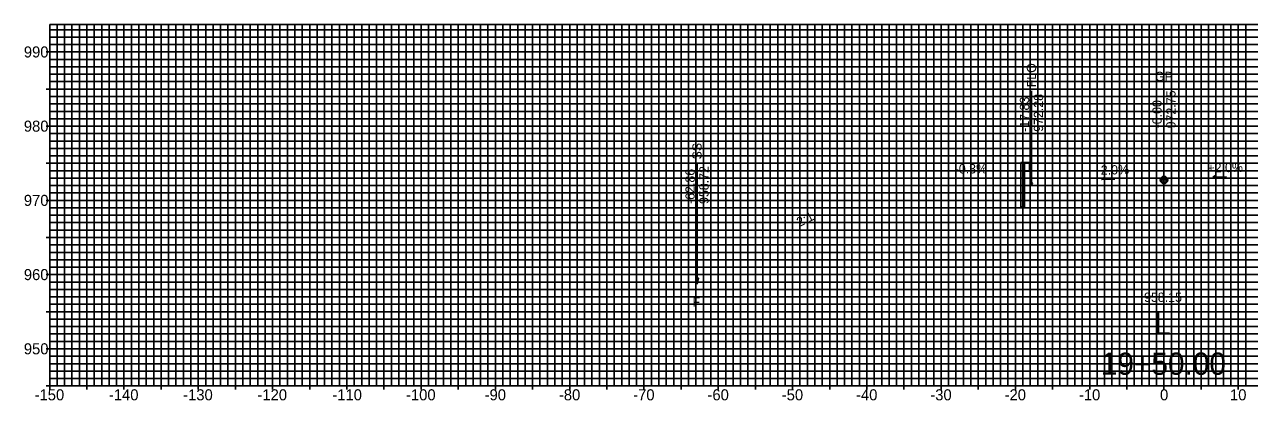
# Model space of a CAD drawing. Extents: x -153 to 153, y 943 to 994.
# Drawn here: x -153.4 to 11.5, y 943 to 993.7 of the extents above; entities that cross this region are included whole.
import ezdxf

# ---------------------------------------------------------------- set-up
doc = ezdxf.new("R2010")
doc.units = 0
for name, color, linetype in [('E_NCDOT_Terrain_Model_Boundary', 7, 'Continuous'), ('E_NCDOT_Terrain_Model_Breakline', 7, 'Continuous'), ('E_NCDOT_Terrain_Model_Hole', 7, 'Continuous'), ('E_NCDOT_Terrain_Model_Island', 7, 'Continuous'), ('E_NCDOT_Terrain_Model_Points_High', 7, 'Continuous'), ('E_NCDOT_Terrain_Model_Points_Low', 7, 'Continuous'), ('E_NCDOT_Terrain_Model_Void', 7, 'Continuous'), ('E_NCDOT_XS_Center_Line_Elevation_Label', 7, 'Continuous'), ('P_NCDOT_XS_Label_Grading_Side_Slope', 7, 'Continuous'), ('P_NCDOT_XS_Label_Slope_Superelevation', 7, 'Continuous'), ('Prop XS Grade Point', 7, 'Continuous'), ('Prop XS Label Slope Superelevation', 7, 'Continuous'), ('Prop XSC Text', 7, 'Continuous'), ('Sheet_Data_Field_CELL', 7, 'Continuous'), ('Sheet_Plan', 7, 'Continuous'), ('Sheet_Sticker_Incomplete_CELL', 7, 'Continuous'), ('z - Construction', 7, 'Continuous')]:
    doc.layers.add(name, color=color, linetype=linetype)

msp = doc.modelspace()

# ---------------------------------------------------------------- linework, layer by layer
at = {"layer": 'E_NCDOT_Terrain_Model_Breakline'}
for p, q in [((-150, 993), (150, 993)), ((-149, 945), (-149, 993.7)), ((-148, 945), (-148, 993.7)), ((-147, 945), (-147, 993.7)), ((-146, 945), (-146, 993.7)), ((-144, 945), (-144, 993.7)), ((-143, 945), (-143, 993.7)), ((-142, 945), (-142, 993.7)), ((-141, 945), (-141, 993.7)), ((-139, 945), (-139, 993.7)), ((-138, 945), (-138, 993.7)), ((-137, 945), (-137, 993.7)), ((-136, 945), (-136, 993.7)), ((-134, 945), (-134, 993.7)), ((-133, 945), (-133, 993.7)), ((-132, 945), (-132, 993.7)), ((-131, 945), (-131, 993.7)), ((-129, 945), (-129, 993.7)), ((-128, 945), (-128, 993.7)), ((-127, 945), (-127, 993.7)), ((-126, 945), (-126, 993.7)), ((-124, 945), (-124, 993.7)), ((-123, 945), (-123, 993.7)), ((-122, 945), (-122, 993.7)), ((-121, 945), (-121, 993.7)), ((-119, 945), (-119, 993.7)), ((-118, 945), (-118, 993.7)), ((-117, 945), (-117, 993.7)), ((-116, 945), (-116, 993.7)), ((-114, 945), (-114, 993.7)), ((-113, 945), (-113, 993.7)), ((-112, 945), (-112, 993.7)), ((-111, 945), (-111, 993.7)), ((-109, 945), (-109, 993.7)), ((-108, 945), (-108, 993.7)), ((-107, 945), (-107, 993.7)), ((-106, 945), (-106, 993.7)), ((-104, 945), (-104, 993.7)), ((-103, 945), (-103, 993.7)), ((-102, 945), (-102, 993.7)), ((-101, 945), (-101, 993.7)), ((-99, 945), (-99, 993.7)), ((-98, 945), (-98, 993.7)), ((-97, 945), (-97, 993.7)), ((-96, 945), (-96, 993.7)), ((-94, 945), (-94, 993.7)), ((-93, 945), (-93, 993.7)), ((-92, 945), (-92, 993.7)), ((-91, 945), (-91, 993.7)), ((-89, 945), (-89, 993.7)), ((-88, 945), (-88, 993.7)), ((-87, 945), (-87, 993.7)), ((-86, 945), (-86, 993.7)), ((-84, 945), (-84, 993.7)), ((-83, 945), (-83, 993.7)), ((-82, 945), (-82, 993.7)), ((-81, 945), (-81, 993.7)), ((-79, 945), (-79, 993.7)), ((-78, 945), (-78, 993.7)), ((-77, 945), (-77, 993.7)), ((-76, 945), (-76, 993.7)), ((-74, 945), (-74, 993.7)), ((-73, 945), (-73, 993.7)), ((-72, 945), (-72, 993.7)), ((-71, 945), (-71, 993.7)), ((-69, 945), (-69, 993.7)), ((-68, 945), (-68, 993.7)), ((-67, 945), (-67, 993.7)), ((-66, 945), (-66, 993.7)), ((-64, 945), (-64, 993.7)), ((-63, 945), (-63, 993.7)), ((-62, 945), (-62, 993.7)), ((-61, 945), (-61, 993.7)), ((-59, 945), (-59, 993.7)), ((-58, 945), (-58, 993.7)), ((-57, 945), (-57, 993.7)), ((-56, 945), (-56, 993.7)), ((-54, 945), (-54, 993.7)), ((-53, 945), (-53, 993.7)), ((-52, 945), (-52, 993.7)), ((-51, 945), (-51, 993.7)), ((-49, 945), (-49, 993.7)), ((-48, 945), (-48, 993.7)), ((-47, 945), (-47, 993.7)), ((-46, 945), (-46, 993.7)), ((-44, 945), (-44, 993.7)), ((-43, 945), (-43, 993.7)), ((-42, 945), (-42, 993.7)), ((-41, 945), (-41, 993.7)), ((-39, 945), (-39, 993.7)), ((-38, 945), (-38, 993.7)), ((-37, 945), (-37, 993.7)), ((-36, 945), (-36, 993.7)), ((-34, 945), (-34, 993.7)), ((-33, 945), (-33, 993.7)), ((-32, 945), (-32, 993.7)), ((-31, 945), (-31, 993.7)), ((-29, 945), (-29, 993.7)), ((-28, 945), (-28, 993.7)), ((-27, 945), (-27, 993.7)), ((-26, 945), (-26, 993.7)), ((-24, 945), (-24, 993.7)), ((-23, 945), (-23, 993.7)), ((-22, 945), (-22, 993.7)), ((-21, 945), (-21, 993.7)), ((-19, 945), (-19, 993.7)), ((-18, 945), (-18, 993.7)), ((-17, 945), (-17, 993.7)), ((-16, 945), (-16, 993.7)), ((-14, 945), (-14, 993.7)), ((-13, 945), (-13, 993.7)), ((-12, 945), (-12, 993.7)), ((-11, 945), (-11, 993.7)), ((-9, 945), (-9, 993.7)), ((-8, 945), (-8, 993.7)), ((-7, 945), (-7, 993.7)), ((-6, 945), (-6, 993.7)), ((-4, 945), (-4, 993.7)), ((-3, 945), (-3, 993.7)), ((-2, 945), (-2, 993.7)), ((-1, 945), (-1, 993.7)), ((1, 945), (1, 993.7)), ((2, 945), (2, 993.7)), ((3, 945), (3, 993.7)), ((4, 945), (4, 993.7)), ((6, 945), (6, 993.7)), ((7, 945), (7, 993.7)), ((8, 945), (8, 993.7)), ((9, 945), (9, 993.7)), ((11, 945), (11, 993.7)), ((-150, 992), (150, 992)), ((-150, 991), (150, 991)), ((-150, 989), (150, 989)), ((-150, 988), (150, 988)), ((-150, 987), (150, 987)), ((-150, 986), (150, 986)), ((-150, 984), (150, 984)), ((-150, 983), (150, 983)), ((-150, 982), (150, 982)), ((-150, 981), (150, 981)), ((-150, 979), (150, 979)), ((-150, 978), (150, 978)), ((-150, 977), (150, 977)), ((-150, 976), (150, 976)), ((-150, 974), (150, 974)), ((-150, 973), (150, 973)), ((-150, 972), (150, 972)), ((-150, 971), (150, 971)), ((-150, 969), (150, 969)), ((-150, 968), (150, 968)), ((-150, 967), (150, 967)), ((-150, 966), (150, 966)), ((-150, 964), (150, 964)), ((-150, 963), (150, 963)), ((-150, 962), (150, 962)), ((-150, 961), (150, 961)), ((-150, 959), (150, 959)), ((-150, 958), (150, 958)), ((-150, 957), (150, 957)), ((-150, 956), (150, 956)), ((-150, 954), (150, 954)), ((-150, 953), (150, 953)), ((-150, 952), (150, 952)), ((-150, 951), (150, 951)), ((-150, 949), (150, 949)), ((-150, 948), (150, 948)), ((-150, 947), (150, 947)), ((-150, 946), (150, 946))]:
    msp.add_line(p, q, dxfattribs=at)
at = {"layer": 'E_NCDOT_Terrain_Model_Island'}
for p, q in [((-140, 945), (-140, 993.7)), ((-130, 945), (-130, 993.7)), ((-120, 945), (-120, 993.7)), ((-110, 945), (-110, 993.7)), ((-100, 945), (-100, 993.7)), ((-90, 945), (-90, 993.7)), ((-80, 945), (-80, 993.7)), ((-70, 945), (-70, 993.7)), ((-60, 945), (-60, 993.7)), ((-50, 945), (-50, 993.7)), ((-40, 945), (-40, 993.7)), ((-30, 945), (-30, 993.7)), ((-20, 945), (-20, 993.7)), ((-10, 945), (-10, 993.7)), ((0, 945), (0, 993.7)), ((10, 945), (10, 993.7)), ((-150, 990), (150, 990)), ((-150, 980), (150, 980)), ((-150, 970), (150, 970)), ((-150, 960), (150, 960)), ((-150, 950), (150, 950))]:
    msp.add_line(p, q, dxfattribs=at)
at = {"layer": 'E_NCDOT_Terrain_Model_Points_High'}
for p, q in [((-145, 945), (-145, 993.7)), ((-140, 945), (-140, 993.7)), ((-135, 945), (-135, 993.7)), ((-130, 945), (-130, 993.7)), ((-125, 945), (-125, 993.7)), ((-120, 945), (-120, 993.7)), ((-115, 945), (-115, 993.7)), ((-110, 945), (-110, 993.7)), ((-105, 945), (-105, 993.7)), ((-100, 945), (-100, 993.7)), ((-95, 945), (-95, 993.7)), ((-90, 945), (-90, 993.7)), ((-85, 945), (-85, 993.7)), ((-80, 945), (-80, 993.7)), ((-75, 945), (-75, 993.7)), ((-70, 945), (-70, 993.7)), ((-65, 945), (-65, 993.7)), ((-60, 945), (-60, 993.7)), ((-55, 945), (-55, 993.7)), ((-50, 945), (-50, 993.7)), ((-45, 945), (-45, 993.7)), ((-40, 945), (-40, 993.7)), ((-35, 945), (-35, 993.7)), ((-30, 945), (-30, 993.7)), ((-25, 945), (-25, 993.7)), ((-20, 945), (-20, 993.7)), ((-15, 945), (-15, 993.7)), ((-10, 945), (-10, 993.7)), ((-5, 945), (-5, 993.7)), ((0, 945), (0, 993.7)), ((5, 945), (5, 993.7)), ((10, 945), (10, 993.7)), ((-150, 990), (-150.48, 990)), ((-150, 990), (150, 990)), ((-150, 985), (-150.48, 985)), ((-150, 985), (150, 985)), ((-150, 980), (-150.48, 980)), ((-150, 980), (150, 980)), ((-150, 975), (-150.48, 975)), ((-150, 975), (150, 975)), ((-150, 970), (-150.48, 970)), ((-150, 970), (150, 970)), ((-150, 965), (-150.48, 965)), ((-150, 965), (150, 965)), ((-150, 960), (-150.48, 960)), ((-150, 960), (150, 960)), ((-150, 955), (-150.48, 955)), ((-150, 955), (150, 955)), ((-150, 950), (-150.48, 950)), ((-150, 950), (150, 950)), ((-150, 945), (-150.48, 945)), ((-150, 945), (-150, 944.52)), ((-145, 945), (-145, 944.52)), ((-140, 945), (-140, 944.52)), ((-135, 945), (-135, 944.52)), ((-130, 945), (-130, 944.52)), ((-125, 945), (-125, 944.52)), ((-120, 945), (-120, 944.52)), ((-115, 945), (-115, 944.52)), ((-110, 945), (-110, 944.52)), ((-105, 945), (-105, 944.52)), ((-100, 945), (-100, 944.52)), ((-95, 945), (-95, 944.52)), ((-90, 945), (-90, 944.52)), ((-85, 945), (-85, 944.52)), ((-80, 945), (-80, 944.52)), ((-75, 945), (-75, 944.52)), ((-70, 945), (-70, 944.52)), ((-65, 945), (-65, 944.52)), ((-60, 945), (-60, 944.52)), ((-55, 945), (-55, 944.52)), ((-50, 945), (-50, 944.52)), ((-45, 945), (-45, 944.52)), ((-40, 945), (-40, 944.52)), ((-35, 945), (-35, 944.52)), ((-30, 945), (-30, 944.52)), ((-25, 945), (-25, 944.52)), ((-20, 945), (-20, 944.52)), ((-15, 945), (-15, 944.52)), ((-10, 945), (-10, 944.52)), ((-5, 945), (-5, 944.52)), ((0, 945), (0, 944.52)), ((5, 945), (5, 944.52)), ((10, 945), (10, 944.52))]:
    msp.add_line(p, q, dxfattribs=at)
at = {"layer": 'E_NCDOT_Terrain_Model_Points_Low'}
for p, q in [((-150, 993.7), (150, 993.7)), ((-150, 945), (-150, 993.7)), ((-150, 945), (150, 945))]:
    msp.add_line(p, q, dxfattribs=at)
at = {"layer": 'E_NCDOT_XS_Center_Line_Elevation_Label'}
for p, q in [((0, 973.25), (0, 972.25)), ((-0.5, 972.75), (0.5, 972.75))]:
    msp.add_line(p, q, dxfattribs=at)
for points in [[(-0.5, 972.75), (0, 972.75), (0, 973.25)], [(0.5, 972.75), (0, 972.75), (0, 972.25)]]:
    msp.add_lwpolyline(points, dxfattribs=at)
msp.add_circle((0, 972.75), 0.5, dxfattribs=at)
for start, end in [(90, 180), (270, 0)]:
    msp.add_arc((0, 972.75), 0.5, start, end, dxfattribs=at)
at = {"layer": 'Prop XS Grade Point'}
for p, q in [((-17.83, 972.28), (-17.83, 984.76)), ((0, 972.75), (0, 985.23)), ((-62.86, 958.72), (-62.86, 974.92))]:
    msp.add_line(p, q, dxfattribs=at)
for points in [[(0.3, 972.45), (-0.3, 972.45), (-0.3, 973.05), (0.3, 973.05)], [(-62.86, 958.72), (-63.04, 959.54), (-62.68, 959.54)]]:
    msp.add_lwpolyline(points, close=True, dxfattribs=at)
msp.add_circle((-17.83, 972.28), 0.12, dxfattribs=at)
at = {"layer": 'Prop XSC Text'}
for p, q in [((-18.78, 975.12), (-19.28, 975.12)), ((-19.28, 975.12), (-19.26, 975.12)), ((-19.28, 969.12), (-19.28, 975.12)), ((-19.26, 975.12), (-19.26, 969.12)), ((-18.79, 975.12), (-18.78, 975.12)), ((-18.79, 969.12), (-18.79, 975.12)), ((-18.78, 975.12), (-18.11, 975.12)), ((-18.78, 975.12), (-18.78, 969.12)), ((-18.11, 975.12), (-18.11, 973.95)), ((-18.1, 975.04), (-18.02, 975.03)), ((-17.87, 974.79), (-18.08, 974.65)), ((-18, 975.02), (-17.87, 974.92)), ((-18.11, 973.95), (-18.78, 973.95)), ((-18.11, 974.59), (-18.11, 974.54)), ((-18.11, 974.54), (-18.11, 974.49)), ((-18.02, 974.05), (-18.1, 974.03)), ((-18.08, 974.43), (-17.87, 974.28)), ((-17.87, 974.15), (-18, 974.06)), ((-18.78, 969.12), (-19.28, 969.12)), ((-19.26, 969.12), (-19.28, 969.12)), ((-18.78, 969.12), (-18.79, 969.12))]:
    msp.add_line(p, q, dxfattribs=at)
for centre, radius, start, end in [((-18.03, 974.59), 0.0787, 124.6522, 179.98), ((-18.02, 974.99), 0.0328, 54.7024, 80), ((-17.91, 974.86), 0.0787, 304.6522, 54.7024), ((-18.03, 974.49), 0.0787, 180.02, 235.3478), ((-18.02, 974.08), 0.0328, 280, 305.2976), ((-17.91, 974.22), 0.0787, 305.2976, 55.3478)]:
    msp.add_arc(centre, radius, start, end, dxfattribs=at)
at = {"layer": 'Sheet_Data_Field_CELL'}
msp.add_line((-15, 972.45), (-15, 973.08), dxfattribs=at)
at = {"layer": 'Sheet_Plan'}
for p, q in [((-8.4, 972.83), (-8.06, 973.07)), ((6.6, 973.13), (6.94, 973.37)), ((8.4, 973.16), (6.6, 973.13)), ((-6.6, 972.86), (-8.4, 972.83))]:
    msp.add_line(p, q, dxfattribs=at)

# ---------------------------------------------------------------- texts
at = {"layer": 'E_NCDOT_Terrain_Model_Boundary'}
for s, height, p in [('990', 1.488, (-153.48, 989.26)), ('980', 1.488, (-153.48, 979.26)), ('970', 1.488, (-153.48, 969.26)), ('960', 1.488, (-153.48, 959.26)), ('950', 1.488, (-153.48, 949.26)), ('-150', 1.488, (-152.03, 943.06)), ('-140', 1.488, (-142.03, 943.06)), ('-130', 1.488, (-132.03, 943.06)), ('-120', 1.488, (-122.03, 943.06)), ('-110', 1.488, (-111.95, 943.06)), ('-100', 1.488, (-102.03, 943.06)), ('-90', 1.488, (-91.45, 943.06)), ('-80', 1.488, (-81.45, 943.06)), ('-70', 1.488, (-71.45, 943.06)), ('-60', 1.488, (-61.45, 943.06)), ('-50', 1.488, (-51.45, 943.06)), ('-40', 1.488, (-41.45, 943.06)), ('-30', 1.488, (-31.45, 943.06)), ('-20', 1.488, (-21.45, 943.06)), ('-10', 1.488, (-11.45, 943.06)), ('0', 1.49, (-0.53, 943.06)), ('10', 1.488, (8.89, 943.06))]:
    msp.add_text(s, height=height, dxfattribs=at).set_placement(p)
at = {"layer": 'E_NCDOT_Terrain_Model_Hole'}
for s, p in [('L', (-1.32, 951.9)), ('19+50.00', (-8.5, 946.5))]:
    msp.add_text(s, height=3, dxfattribs=at).set_placement(p)
at = {"layer": 'E_NCDOT_Terrain_Model_Void'}
for s, p in [('-2.0%', (-9.05, 973.45)), ('+2.0%', (5.86, 973.75))]:
    msp.add_text(s, height=1.248, rotation=1.1458, dxfattribs=at).set_placement(p)
at = {"layer": 'P_NCDOT_XS_Label_Grading_Side_Slope'}
for s, rotation, p in [('-0.3%', 0.1862, (-28.17, 973.63)), ('2:1', 26.5651, (-49.07, 966.41))]:
    msp.add_text(s, height=1.248, rotation=rotation, dxfattribs=at).set_placement(p)
at = {"layer": 'P_NCDOT_XS_Label_Slope_Superelevation'}
msp.add_text('GP', height=1.248, dxfattribs=at).set_placement((-1.22, 986.08))
for s, p in [('972.75', (1.56, 979.71)), ('-17.83', (-18.15, 979.24)), ('972.28', (-16.27, 979.24)), ('-0.00', (-0.31, 979.71))]:
    msp.add_text(s, height=1.248, rotation=90, dxfattribs=at).set_placement(p)
at = {"layer": 'Prop XS Label Slope Superelevation'}
for s, p in [('SS', (-62.24, 975.52)), ('-62.86', (-63.17, 969.52)), ('958.72', (-61.3, 969.52))]:
    msp.add_text(s, height=1.248, rotation=90, dxfattribs=at).set_placement(p)
msp.add_text('F', height=1.25, dxfattribs=at).set_placement((-63.46, 955.69))
at = {"layer": 'Sheet_Sticker_Incomplete_CELL'}
msp.add_text('FLO', height=1.248, rotation=90, dxfattribs=at).set_placement((-17.21, 985.24))
at = {"layer": 'z - Construction'}
msp.add_text('958.15', height=1.248, dxfattribs=at).set_placement((-2.68, 956.33))

doc.saveas('drawing.dxf')
